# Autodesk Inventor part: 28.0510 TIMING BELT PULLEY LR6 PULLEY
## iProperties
Created: 2007-06
Part Number: 28.0510 TIMING BELT PULLEY LR6 PULLEY
Document SubType Name: Modeling
Designer: Andy Moles
Material: Aluminum-6061
Density: 2.71 g/cm^3
Mass: 139.14 g
Surface Area: 162.222 cm^2
Volume: 51.3432 cm^3
Author: Andy Moles
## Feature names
1. Revolution1
2. Extrusion1
3. Circular Pattern1
4. Extrusion2
5. Mirror1
6. Chamfer1
